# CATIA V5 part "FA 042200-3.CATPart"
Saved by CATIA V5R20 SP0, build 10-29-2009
Part number: FA 042200-3
Revision: ANY
Definition: UNKNOWN
Nomenclature: FA 042200-3
Source: Unknown
Bounding box of the stored display mesh (mm): x 0 to 2, y -1.45 to 1.45, z -1.45 to 1.45
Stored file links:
  C:\Users\Utente\Desktop\IO LAVORO\3D X SITO CF\CUMSA\3D files FA\FA 0422SF\FA 042200-3.CATPart

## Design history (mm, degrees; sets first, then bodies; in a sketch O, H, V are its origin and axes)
Body1 "Revolución1" (main body)
  Solid1: solid without history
